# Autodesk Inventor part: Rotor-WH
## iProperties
Created: 2008-07
Part Number: Rotor-WH
Document SubType Name: Modeling
Designer: WH
Density: 1 g/cm^3
Author: WH
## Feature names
1. Basis1
2. Bohrung1 [Hole]
3. Extrusion1
